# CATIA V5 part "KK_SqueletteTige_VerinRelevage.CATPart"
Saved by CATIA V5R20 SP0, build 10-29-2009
Part number: Squelette_tige_verin_de_relevage
Bounding box of the stored display mesh (mm): x -273.14 to -256, y -200 to 200, z -1280 to -320.153
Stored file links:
  G:\Khaled_CFAO_2011\ST2M\ST2M_GR2\aboulegue\Khaled\CAD_thinkMOTION\KK_SqueletteTige_VerinRelevage.CATPart
  G:\Khaled_CFAO_2011\ST2M\ST2M_GR2\aboulegue\Khaled\CAD_thinkMOTION\KK_Train_Atterrissage.CATProduct
  G:\Khaled_CFAO_2011\ST2M\ST2M_GR2\aboulegue\CFAO_aboulegue\CFAO_aboulegue_fichiers_catia\Squelette_panneau_pivotant.CATPart
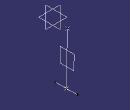
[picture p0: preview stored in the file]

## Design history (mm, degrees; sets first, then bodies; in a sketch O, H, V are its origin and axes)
Set1
  Point1 "Point.10": linked copy from another document
  Point2 "Point.21": linked copy from another document
  Plane1 "Plan reference 2": linked copy from another document
Set2 "Set squelette verin de relevage"
  Line1: type PtPt, FirstPoint Point1, SecondPoint Point2
  Line2: type Normal, RefPoint Point1, RefSkin Plane1, Start -200, End 200
  Plane2 "Plan de reference tige de verin de relevage": type 2Lines, Element1 Line1, Element2 Line2
Body1 (main body)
